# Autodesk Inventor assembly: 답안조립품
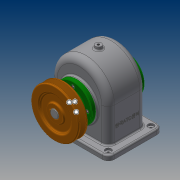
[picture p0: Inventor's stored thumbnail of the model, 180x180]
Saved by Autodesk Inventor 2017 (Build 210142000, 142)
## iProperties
Part Number: 답안조립품
Material: 일반
Document SubType Name: Assembly
Designer: 20
Author: 20
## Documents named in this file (14)
- C:\Users\20\Desktop\480310V1002\답안조립품.iam
- C:\Users\20\Desktop\480310V1002\본체.ipt
- C:\Users\20\Desktop\480310V1002\앞커버.ipt
- C:\Users\20\Desktop\480310V1002\뒤커버.ipt
- C:\Users\20\Desktop\480310V1002\볼트 M4.ipt
- C:\Users\20\Desktop\480310V1002\베어링 6203.ipt
- C:\Users\20\Desktop\480310V1002\축.ipt
- C:\Users\20\Desktop\480310V1002\스퍼기어.ipt
- C:\Users\20\Desktop\480310V1002\키 6x6x22.ipt
- C:\Users\20\Desktop\480310V1002\부시.ipt
- C:\Users\20\Desktop\480310V1002\V-벨트풀리.ipt
- C:\Users\20\Desktop\480310V1002\멈춤나사 M4.ipt
- C:\Users\20\Desktop\480310V1002\키 5x5x18.ipt
- C:\Users\20\Desktop\480310V1002\오일 실 28 40 8.ipt
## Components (1 placed, 1 different names)
1. V-벨트풀리:1 — 플러쉬:2
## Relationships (1: Flush 1)
- 플러쉬:2 [Flush]: V-벨트풀리:1
